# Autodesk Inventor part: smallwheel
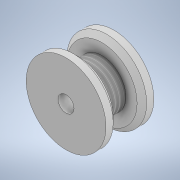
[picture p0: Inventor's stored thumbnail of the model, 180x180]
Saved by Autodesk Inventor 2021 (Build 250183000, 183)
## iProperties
Created: 2021-06
Part Number: smallwheel
Material: Generic
Document SubType Name: Modeling
Designer: Astami
Density: 1 g/cm^3
Appearance: Default
Author: Astami
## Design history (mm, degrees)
sketch "Sketch1"
  geometry: C1 r 50 at (0, 0); 1 further point
  constraints: 1 centre point, 1 coincident
  dimensions: "d0" = 100 diameter of C1
extrude "Extrusion1" new body sketch "Sketch1" distance "d1" = 15; taper "d2" = 0 deg
sketch "Sketch2"
  geometry: C1 r 30 at (0, 0); 1 further point
  constraints: 1 centre point, 1 coincident
  dimensions: "d3" = 60 diameter of C1
extrude "Extrusion2" join sketch "Sketch2" distance "d4" = 30; taper "d5" = 0 deg
sketch "Sketch3"
  geometry: C1 r 50 at (0, 0); 1 further point
  constraints: 1 centre point, 1 coincident
  dimensions: "d6" = 100 diameter of C1
extrude "Extrusion3" join sketch "Sketch3" distance "d7" = 15; taper "d8" = 0 deg
thread "Thread1" dims "d9" = 49.433, "d10" = 0
chamfer "Chamfer1" distance "d11" = 6; stored, may be unused: second distance "d12" = 2, angle "d13" = 45 deg
chamfer "Chamfer2" distance "d14" = 6; stored, may be unused: second distance "d15" = 2, angle "d16" = 45 deg
sketch "Sketch4"
  geometry: C1 r 10 at (0, 0); 1 further point
  constraints: 1 centre point, 1 coincident
  dimensions: "d17" = 20 diameter of C1
extrude "Extrusion4" cut sketch "Sketch4" extent not by distance; stored distance "d18" = 0; taper "d19" = 0 deg
body "Solid1"
